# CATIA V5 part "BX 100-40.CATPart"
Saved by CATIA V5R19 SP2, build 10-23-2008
Part number: BX 100-40
Bounding box of the stored display mesh (mm): x -18.951 to 18.951, y -18.952 to 18.952, z 0 to 195
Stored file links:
  C:\Users\Bora\Desktop\3D Katı model\BX serisi\BX 100\BX 100-40.CATPart
  C:\Program Files\Dassault Systemes\B19\intel_a\reffiles\standard\MetricThickPitch.txt
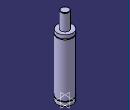
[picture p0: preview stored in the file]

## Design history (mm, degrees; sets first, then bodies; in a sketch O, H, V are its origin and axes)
Body1 (main body)
  Sketch1 on yz-plane, origin (0, 0, 0), H (0, 1, 0), V (0, 0, 1)
    point P2 (19, 9.5)
    line L1 (19, 9.5) -> (19, 0)
    point P3 (19, 9.5)
    point P4 (19, 11.5)
    arc A1 centre (19, 10.5) radius 1 from (19, 11.5) to (19, 9.5) ccw
    point P5 (19, 11.5)
    point P6 (19, 143.5)
    line L2 (19, 143.5) -> (19, 11.5)
    point P7 (19, 143.5)
    point P8 (19, 145.5)
    arc A2 centre (19, 144.5) radius 1 from (19, 145.5) to (19, 143.5) ccw
    point P10 (10, 194)
    arc A3 centre (9, 194) radius 1 from (10, 194) to (9, 195) ccw
    point P12 (10, 194)
    line L3 (10, 194) -> (10, 154)
    point P13 (19, 145.5)
    line L4 (19, 154) -> (19, 145.5)
    line L5 (9, 195) -> (0, 195)
    point P15 (0, 195)
    line L6 (10, 154) -> (19, 154)
    line L7 (19, 0) -> (0, 0)
    tangency: L5 A3
    coincidence: P15 V, P2 P3, P4 P5, P6 P7, P8 P13, P10 P12
    horizontal: L6 H, L7 H
  Shaft1: profile Sketch1, axis Sketch1.V, angle 360
  Sketch2 on face of Shaft1 from Sketch1.L7, origin (0, 0, 0), H (1, 0, 0), V (0, -1, 0)
    point P1 (9, 0)
    distance P1 V = 9
  Hole1: placed by Sketch2, at (9, 0, 0) direction (0, 0, 1), diameter 4.917, depth 6, threaded "M6", thread diameter 6, thread depth 6, pitch 1
  Sketch3 on face of Shaft1 from Sketch1.L7, origin (0, 0, 0), H (1, 0, 0), V (0, -1, 0)
    point P1 (-9, 0)
    distance P1 V = 9
  Hole2: placed by Sketch3, at (-9, 0, 0) direction (0, 0, 1), diameter 4.917, depth 6, threaded "M6", thread diameter 6, thread depth 6, pitch 1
